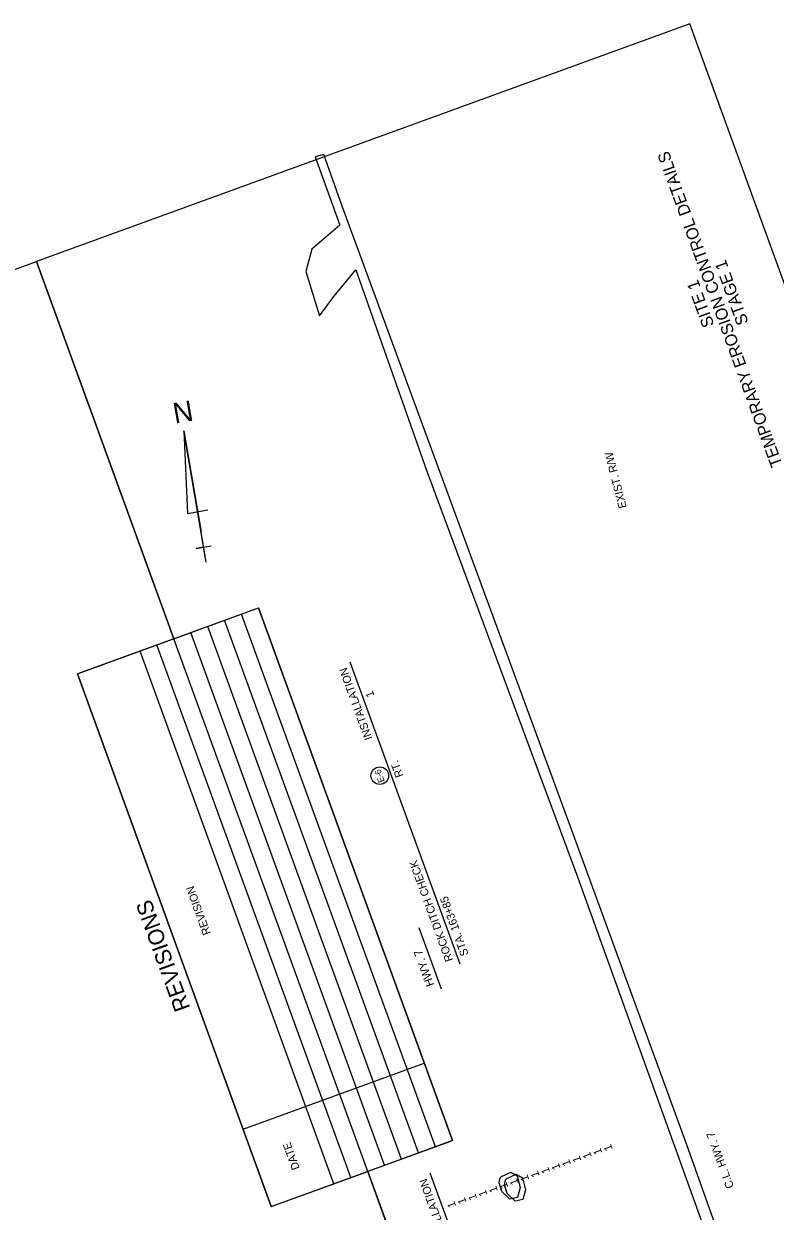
# Model space of a CAD drawing. Extents: x 986289 to 987754, y 1871116 to 1872971.
# Drawn here: x 986709 to 987265, y 1872081 to 1872971 of the extents above; entities that cross this region are included whole.
import ezdxf

# ---------------------------------------------------------------- set-up
doc = ezdxf.new("R2010")
doc.units = 0
for name, color, linetype in [('1', 7, 'Continuous'), ('44', 7, 'Continuous'), ('60', 7, 'Continuous'), ('63', 7, 'Continuous'), ('Default', 7, 'Continuous'), ('NO PLOT', 7, 'Continuous'), ('R_Draft', 7, 'Continuous'), ('S_TREE', 7, 'Continuous')]:
    doc.layers.add(name, color=color, linetype=linetype)

msp = doc.modelspace()

# ---------------------------------------------------------------- linework, layer by layer
at = {"layer": '1'}
for p, q in [((986821.23, 1872510.15), (986718.28, 1872792.99)), ((987064.47, 1871841.86), (986966.59, 1872110.78))]:
    msp.add_line(p, q, dxfattribs=at)
msp.add_circle((986975.63, 1872407.47), 6.61, dxfattribs=at)
at = {"layer": '44'}
for p, q in [((987035.86, 1872266.04), (986953.43, 1872492.51)), ((987021.79, 1872247.42), (987005.08, 1872293.32)), ((987095.89, 1871882.86), (987013.46, 1872109.34))]:
    msp.add_line(p, q, dxfattribs=at)
at = {"layer": '63'}
for p, q in [((986845.5, 1872567.48), (986828.63, 1872666.05)), ((986828.63, 1872666.05), (986841.61, 1872590.23)), ((986828.63, 1872666.05), (986831.43, 1872604.09)), ((986831.43, 1872604.09), (986846.59, 1872606.69)), ((986845.5, 1872567.48), (986841.61, 1872590.23)), ((986837.87, 1872577.88), (986849.24, 1872579.83)), ((986843.55, 1872578.85), (986837.87, 1872577.88)), ((986845.5, 1872567.48), (986843.55, 1872578.85))]:
    msp.add_line(p, q, dxfattribs=at)
at = {"layer": 'Default'}
for p, q in [((986748.87, 1872483.82), (986884.66, 1872533.24)), ((987017.33, 1872129.25), (986871.97, 1872528.62)), ((987030.02, 1872133.87), (986884.66, 1872533.24)), ((986991.96, 1872120.02), (986846.6, 1872519.39)), ((987004.65, 1872124.63), (986859.29, 1872524)), ((986966.59, 1872110.78), (986821.23, 1872510.15)), ((986979.27, 1872115.4), (986833.92, 1872514.77)), ((986979.27, 1872115.4), (986833.92, 1872514.77)), ((986941.22, 1872101.55), (986795.86, 1872500.92)), ((986953.9, 1872106.17), (986808.54, 1872505.53)), ((986894.23, 1872084.45), (986748.87, 1872483.82)), ((986873.09, 1872142.53), (987008.88, 1872191.95)), ((986894.23, 1872084.45), (987030.02, 1872133.87))]:
    msp.add_line(p, q, dxfattribs=at)
at = {"layer": 'NO PLOT'}
for points in [[(987753.66, 1871472.09), (987208.01, 1872971.24), (986718.28, 1872792.99), (986821.23, 1872510.15), (986884.66, 1872533.24), (987030.02, 1872133.87), (986966.59, 1872110.78), (987064.47, 1871841.86), (987122.5, 1871862.99), (987239.7, 1871540.99), (987181.66, 1871519.87), (987263.93, 1871293.85)], [(987753.66, 1871472.09), (987208.01, 1872971.24), (986718.28, 1872792.99), (986821.23, 1872510.15), (986884.66, 1872533.24), (987030.02, 1872133.87), (986966.59, 1872110.78), (987064.47, 1871841.86), (987122.5, 1871862.99), (987239.7, 1871540.99), (987181.66, 1871519.87), (987263.93, 1871293.85)], [(987753.66, 1871472.09), (987208.01, 1872971.24), (986718.28, 1872792.99), (986821.23, 1872510.15), (986884.66, 1872533.24), (987030.02, 1872133.87), (986966.59, 1872110.78), (987064.47, 1871841.86), (987122.5, 1871862.99), (987239.7, 1871540.99), (987181.66, 1871519.87), (987263.93, 1871293.85)], [(987753.66, 1871472.09), (987208.01, 1872971.24), (986718.28, 1872792.99), (986821.23, 1872510.15), (986884.66, 1872533.24), (987030.02, 1872133.87), (986966.59, 1872110.78), (987064.47, 1871841.86), (987122.5, 1871862.99), (987239.7, 1871540.99), (987181.66, 1871519.87), (987263.93, 1871293.85)], [(987491.83, 1871372.7), (987456.23, 1871457.1), (987369.24, 1871671.93), (987295.12, 1871880.05), (987205.8, 1872130.82), (987120.96, 1872363.03), (986947.4, 1872834.51), (986933.66, 1872873.15), (986927.12, 1872871.42), (986945.75, 1872820.24), (986924.65, 1872802.14), (986920.25, 1872785.56), (986930.46, 1872752.16), (986941.1, 1872766.78), (986957.6, 1872786.78), (987010.89, 1872635.88), (987123.94, 1872331.56), (987288.16, 1871875.89), (987395.43, 1871570.43), (987485.29, 1871370.98)], [(986774.2, 1871115.6), (986369.23, 1872228.25), (986415.65, 1872245.15), (986348.68, 1872429.14), (986362.4, 1872434.13), (986288.69, 1872636.64), (986718.28, 1872792.99), (986821.23, 1872510.15), (986748.87, 1872483.82), (986894.23, 1872084.45), (986966.59, 1872110.78), (987064.47, 1871841.86), (987008.75, 1871821.58), (987125.95, 1871499.59), (987181.66, 1871519.87), (987263.93, 1871293.85)], [(986774.2, 1871115.6), (986369.23, 1872228.25), (986415.65, 1872245.15), (986348.68, 1872429.14), (986362.4, 1872434.13), (986288.69, 1872636.64), (986718.28, 1872792.99), (986821.23, 1872510.15), (986748.87, 1872483.82), (986894.23, 1872084.45), (986966.59, 1872110.78), (987064.47, 1871841.86), (987008.75, 1871821.58), (987125.95, 1871499.59), (987181.66, 1871519.87), (987263.93, 1871293.85)], [(986774.2, 1871115.6), (986369.23, 1872228.25), (986415.65, 1872245.15), (986348.68, 1872429.14), (986362.4, 1872434.13), (986288.69, 1872636.64), (986718.28, 1872792.99), (986821.23, 1872510.15), (986748.87, 1872483.82), (986894.23, 1872084.45), (986966.59, 1872110.78), (987064.47, 1871841.86), (987008.75, 1871821.58), (987125.95, 1871499.59), (987181.66, 1871519.87), (987263.93, 1871293.85)], [(986774.2, 1871115.6), (986369.23, 1872228.25), (986415.65, 1872245.15), (986348.68, 1872429.14), (986362.4, 1872434.13), (986288.69, 1872636.64), (986718.28, 1872792.99), (986821.23, 1872510.15), (986748.87, 1872483.82), (986894.23, 1872084.45), (986966.59, 1872110.78), (987064.47, 1871841.86), (987008.75, 1871821.58), (987125.95, 1871499.59), (987181.66, 1871519.87), (987263.93, 1871293.85)]]:
    msp.add_lwpolyline(points, close=True, dxfattribs=at)
at = {"layer": 'S_TREE'}
for points in [[(987066.33, 1872106.68), (987073.81, 1872110.17), (987078.63, 1872107.43), (987080.78, 1872098.6), (987078.85, 1872091.22), (987073.15, 1872089.95), (987067.07, 1872095.83), (987065.21, 1872102.28), (987065.82, 1872105.93), (987067.01, 1872107.15)], [(987070.36, 1872105.15), (987077.83, 1872108.64), (987082.66, 1872105.9), (987084.81, 1872097.07), (987082.87, 1872089.69), (987077.17, 1872088.42), (987071.09, 1872094.3), (987069.23, 1872100.75), (987069.85, 1872104.4), (987071.04, 1872105.62)]]:
    msp.add_lwpolyline(points, dxfattribs=at)

# ---------------------------------------------------------------- texts
at = {"layer": '1'}
msp.add_text('E-6 ', height=4.8, rotation=110, dxfattribs=at).set_placement((986979.37, 1872403.3))
at = {"layer": '44'}
for s, height, p in [('INSTALLATION', 6, (986970.2, 1872435.45)), ('1', 6, (986971.71, 1872467.45)), ('RT.', 6, (986993.38, 1872407.4)), ('ROCK DITCH CHECK', 6, (987030.69, 1872269.26)), ('STA. 163+85', 6, (987042.28, 1872273.48)), ('HWY. 7', 6.25, (987016.58, 1872250.68)), ('1', 6, (987142.53, 1872124.59)), ('1', 6, (987150.32, 1872127.43)), ('1', 6, (987119.04, 1872116.04)), ('1', 6, (987126.83, 1872118.88)), ('1', 6, (987134.66, 1872121.73)), ('1', 6, (987087.76, 1872104.66)), ('1', 6, (987095.59, 1872107.51)), ('1', 6, (987103.38, 1872110.35)), ('1', 6, (987111.21, 1872113.2)), ('INSTALLATION', 6, (987030.23, 1872052.27)), ('1', 6, (987064.27, 1872096.11)), ('1', 6, (987072.1, 1872098.96)), ('1', 6, (987079.89, 1872101.8)), ('1', 6, (987040.82, 1872087.58)), ('1', 6, (987048.65, 1872090.43)), ('1', 6, (987056.44, 1872093.26)), ('1', 6, (987032.99, 1872084.73))]:
    msp.add_text(s, height=height, rotation=110, dxfattribs=at).set_placement(p)
at = {"layer": '60'}
for s, p in [('TEMPORARY EROSION CONTROL DETAILS', (987277.82, 1872640.76)), ('STAGE 1', (987252.25, 1872747.22)), ('SITE 1', (987226.54, 1872745.48))]:
    msp.add_text(s, height=9, rotation=110, dxfattribs=at).set_placement(p)
at = {"layer": '63'}
msp.add_text('N', height=15.38, rotation=9.71442, dxfattribs=at).set_placement((986821.99, 1872671.41))
at = {"layer": 'Default'}
for s, height, p in [('REVISION', 6, (986848.94, 1872289.29)), ('REVISIONS', 12, (986833.67, 1872233.29)), ('DATE', 6, (986915.7, 1872113.17))]:
    msp.add_text(s, height=height, rotation=110, dxfattribs=at).set_placement(p)
at = {"layer": 'R_Draft'}
for s, rotation, p in [('EXIST. R/W', 104.47173, (987160.8, 1872608.78)), ('C.L. HWY. 7', 110.10447, (987241.24, 1872099.26))]:
    msp.add_text(s, height=6, rotation=rotation, dxfattribs=at).set_placement(p)

doc.saveas('drawing.dxf')
